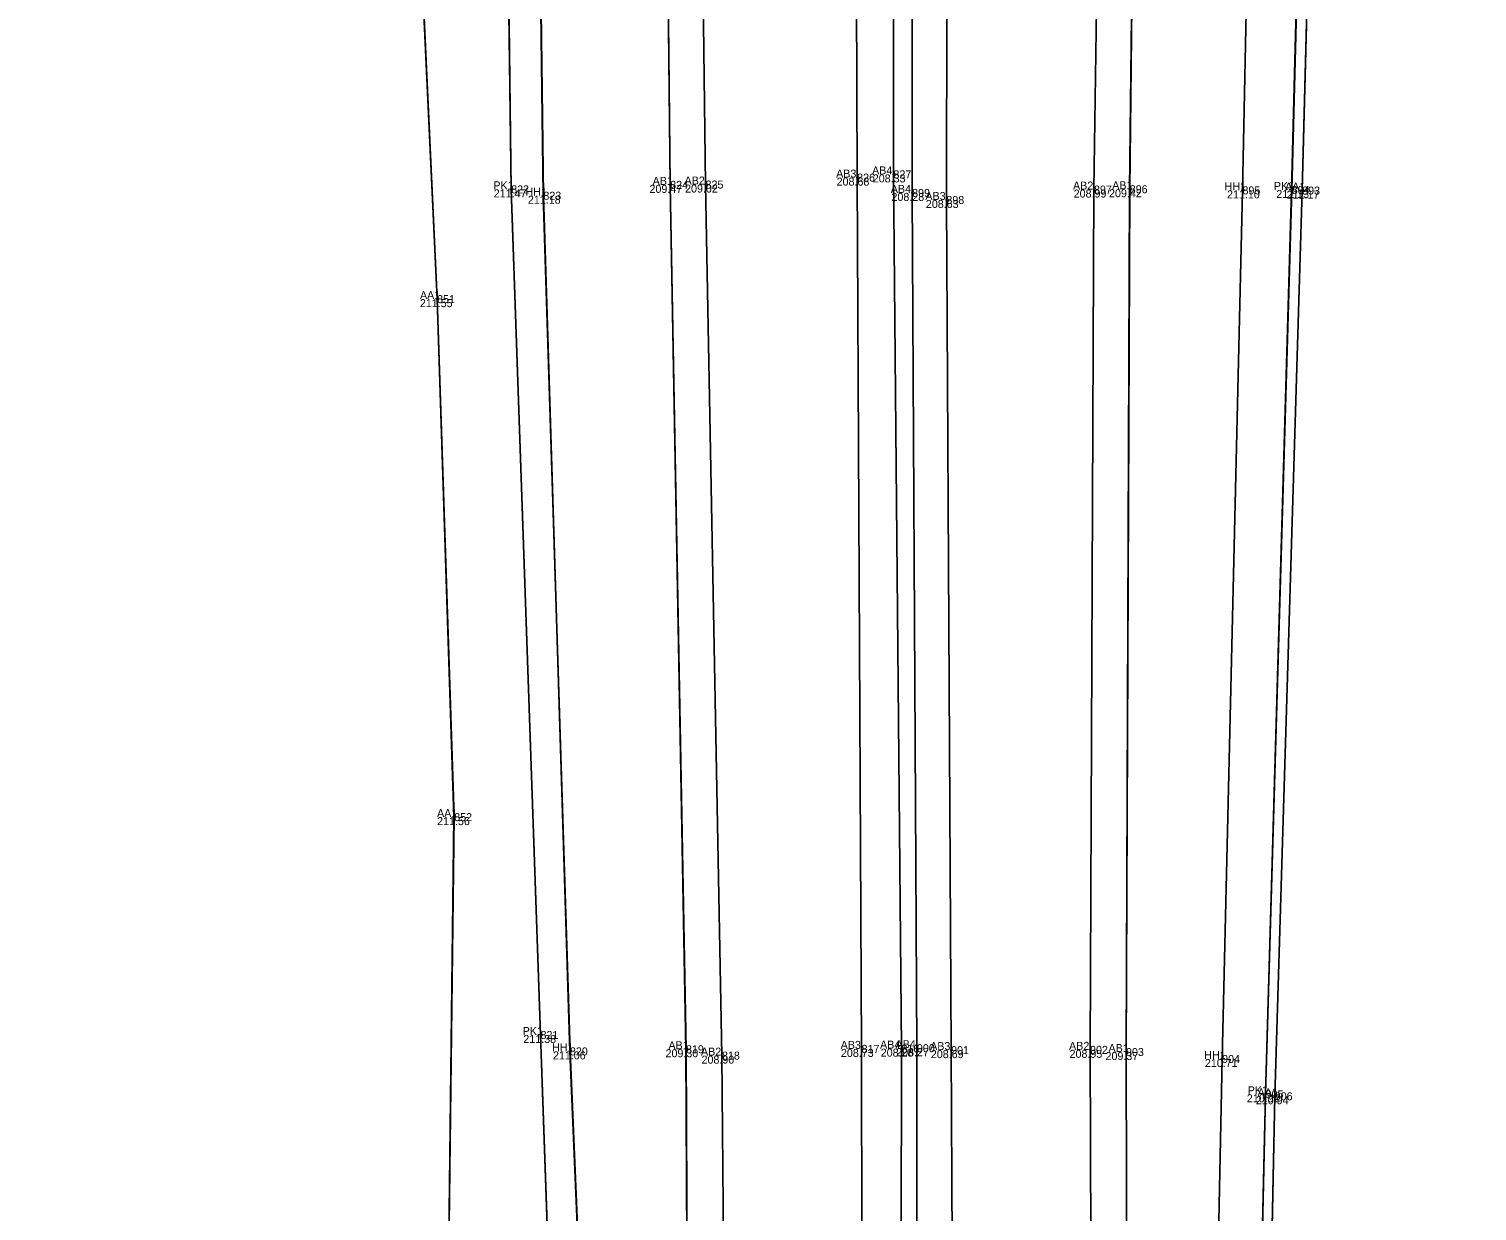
# Model space of a CAD drawing. Extents: x -263091 to -262565, y -1238731 to -1237092.
# Drawn here: x -262760.95 to -262724.75, y -1237381.76 to -1237352.21 of the extents above; entities that cross this region are included whole.
import ezdxf

# ---------------------------------------------------------------- set-up
doc = ezdxf.new("R2010")
doc.units = 0
for name, color, linetype in [('01_Hrana_betónu', 7, 'Continuous'), ('02_Oplotenie', 7, 'Continuous'), ('03_Asfalt', 7, 'Continuous'), ('05_Hrana_terénu', 7, 'Continuous'), ('Groma (21)', 7, 'Continuous'), ('Groma (22)', 7, 'Continuous'), ('Groma (23)', 7, 'Continuous'), ('Groma (24)', 7, 'Continuous'), ('U004_Asfalty', 7, 'Continuous'), ('U005_Betónové_panely', 7, 'Continuous'), ('U005_Zeleň_mimo', 7, 'Continuous'), ('U005_Zeleň_vnútro', 7, 'Continuous'), ('U005_Zeleň_zatrávňovač', 7, 'Continuous')]:
    doc.layers.add(name, color=color, linetype=linetype)

msp = doc.modelspace()

# ---------------------------------------------------------------- linework, layer by layer
at = {"layer": '01_Hrana_betónu'}
for points in [[(-262786.432, -1237675.911), (-262784.052, -1237670.991), (-262777.997, -1237658.39), (-262770.22, -1237641.884), (-262760.517, -1237621.621), (-262751.199, -1237602.266), (-262746.917, -1237592.345), (-262743.67, -1237583.59), (-262741.234, -1237574.416), (-262739.924, -1237566.213), (-262738.929, -1237556.596), (-262738.741, -1237547.665), (-262738.506, -1237524.618), (-262738.316, -1237501.393), (-262738.103, -1237478.98), (-262737.841, -1237459.175), (-262737.82, -1237425.07), (-262737.772, -1237401.714), (-262737.893, -1237377.738), (-262738.012, -1237356.488), (-262737.973, -1237332.295), (-262738.006, -1237318.022), (-262737.947, -1237310.645)], [(-262738.855, -1237311.192), (-262738.946, -1237318.051), (-262738.849, -1237332.413), (-262738.867, -1237356.312), (-262738.748, -1237377.69), (-262738.758, -1237401.69), (-262738.753, -1237425.185), (-262738.668, -1237459.096), (-262739.01, -1237478.875), (-262739.257, -1237501.361), (-262739.436, -1237524.506), (-262739.635, -1237547.624), (-262739.863, -1237556.5), (-262740.784, -1237566.075), (-262742.123, -1237574.161), (-262744.555, -1237583.315), (-262747.793, -1237592.067), (-262752.033, -1237601.877), (-262761.381, -1237621.164), (-262771.059, -1237641.465), (-262778.806, -1237657.918), (-262784.861, -1237670.667), (-262787.201, -1237675.529)], [(-262739.343, -1237311.485), (-262739.423, -1237318.909), (-262739.337, -1237332.42), (-262739.334, -1237355.849), (-262739.135, -1237377.701), (-262739.178, -1237401.786), (-262739.257, -1237424.031), (-262739.458, -1237458.924), (-262739.421, -1237479.296), (-262739.718, -1237500.116), (-262739.917, -1237524.824), (-262740.163, -1237546.913), (-262740.342, -1237556.649), (-262741.144, -1237564.78), (-262742.646, -1237573.838), (-262744.715, -1237582.455), (-262748.007, -1237591.229), (-262752.529, -1237601.669), (-262761.584, -1237620.386), (-262771.44, -1237641.076), (-262779.114, -1237657.574), (-262785.318, -1237670.364), (-262787.643, -1237675.31)], [(-262788.441, -1237674.914), (-262786.102, -1237669.974), (-262779.96, -1237657.146), (-262772.255, -1237640.671), (-262762.405, -1237620.082), (-262753.353, -1237601.237), (-262748.855, -1237590.92), (-262745.54, -1237582.117), (-262743.431, -1237573.688), (-262742.016, -1237564.7), (-262741.168, -1237556.501), (-262740.979, -1237546.892), (-262740.851, -1237524.752), (-262740.671, -1237500.08), (-262740.394, -1237479.483), (-262740.216, -1237458.955), (-262740.117, -1237423.647), (-262740.094, -1237401.75), (-262740.13, -1237377.708), (-262740.243, -1237355.929), (-262740.317, -1237332.345), (-262740.44, -1237318.894), (-262740.323, -1237312.076)], [(-262744.671, -1237314.693), (-262744.322, -1237332.28), (-262744.032, -1237356.103), (-262743.621, -1237377.876), (-262743.427, -1237401.834), (-262743.334, -1237423.507), (-262743.665, -1237455.163), (-262743.89, -1237458.66), (-262743.816, -1237479.543), (-262744.125, -1237500.374), (-262744.256, -1237524.891), (-262744.407, -1237545.149), (-262744.747, -1237556.085), (-262745.544, -1237564.593), (-262746.648, -1237572.023), (-262748.879, -1237581.03), (-262752.099, -1237589.665), (-262756.673, -1237599.828), (-262765.314, -1237617.226), (-262775.804, -1237639.013), (-262783.576, -1237655.372), (-262792.033, -1237673.09)], [(-262792.676, -1237672.47), (-262784.421, -1237654.971), (-262776.677, -1237638.569), (-262766.087, -1237616.912), (-262757.487, -1237599.378), (-262752.942, -1237589.379), (-262749.712, -1237580.796), (-262747.504, -1237571.715), (-262746.486, -1237564.414), (-262745.673, -1237555.98), (-262745.336, -1237545.322), (-262745.216, -1237524.737), (-262745.016, -1237500.506), (-262744.745, -1237479.418), (-262744.873, -1237458.479), (-262744.515, -1237455.206), (-262744.284, -1237423.517), (-262744.408, -1237401.828), (-262744.521, -1237377.717), (-262744.916, -1237356.111), (-262745.155, -1237332.402), (-262745.296, -1237327.881), (-262745.213, -1237324.651), (-262745.472, -1237315.175)], [(-262734.981, -1237524.159), (-262734.838, -1237501.704), (-262734.759, -1237479.135), (-262734.503, -1237458.564), (-262734.325, -1237455.231), (-262734.525, -1237425.166), (-262734.337, -1237401.529), (-262734.42, -1237377.731), (-262734.322, -1237356.228), (-262733.976, -1237332.423), (-262733.848, -1237318.408), (-262733.791, -1237315.943)], [(-262734.294, -1237524.216), (-262733.894, -1237501.859), (-262733.827, -1237479.2), (-262733.643, -1237458.579), (-262733.47, -1237455.059), (-262733.653, -1237425.263), (-262733.458, -1237401.537), (-262733.52, -1237377.786), (-262733.428, -1237356.22), (-262733.164, -1237332.492), (-262733.076, -1237318.46), (-262733.061, -1237316.012)]]:
    msp.add_lwpolyline(points, dxfattribs=at)
at = {"layer": '02_Oplotenie'}
for points in [[(-262728.456, -1237307.793), (-262728.519, -1237318.579), (-262728.768, -1237332.338), (-262729.377, -1237356.238), (-262730.032, -1237378.843), (-262730.564, -1237401.661), (-262730.923, -1237425.563), (-262730.973, -1237458.163), (-262731.252, -1237478.578), (-262731.235, -1237502.529), (-262731.31, -1237524.311), (-262731.953, -1237547.895), (-262732.188, -1237556.779), (-262732.808, -1237567.174), (-262734.162, -1237576.139), (-262736.979, -1237586.017), (-262740.293, -1237594.798), (-262745.086, -1237605.537), (-262753.698, -1237624.773), (-262762.903, -1237643.627), (-262772.016, -1237662.266), (-262776.478, -1237670.97)], [(-262793.971, -1237669.784), (-262786.051, -1237653.784), (-262778.339, -1237638.096), (-262767.839, -1237615.998), (-262759.49, -1237598.413), (-262754.828, -1237588.44), (-262751.768, -1237579.927), (-262749.971, -1237571.226), (-262749.021, -1237564.318), (-262748.215, -1237555.413), (-262747.787, -1237545.2), (-262747.818, -1237524.565), (-262747.681, -1237500.551), (-262747.391, -1237479.445), (-262747.231, -1237460.146), (-262746.875, -1237423.458), (-262747.304, -1237401.954), (-262748.156, -1237377.36), (-262748.89, -1237356.224), (-262749.247, -1237329.045)]]:
    msp.add_lwpolyline(points, dxfattribs=at)
at = {"layer": '03_Asfalt'}
for points in [[(-262724.746, -1237307.401), (-262727.828, -1237308.991), (-262728.093, -1237318.612), (-262728.491, -1237332.383), (-262729.117, -1237356.253), (-262729.803, -1237378.892), (-262730.272, -1237401.612), (-262730.633, -1237425.617), (-262730.625, -1237458.196), (-262731.018, -1237478.61), (-262730.917, -1237502.542), (-262731.001, -1237524.284), (-262731.468, -1237547.904), (-262731.892, -1237556.788), (-262732.535, -1237567.203), (-262733.679, -1237576.214), (-262736.504, -1237586.306), (-262740.104, -1237594.868), (-262744.783, -1237605.686), (-262753.189, -1237625.134), (-262761.527, -1237644.232), (-262769.984, -1237663.306), (-262774.379, -1237673.302), (-262777.928, -1237681.411)], [(-262754.337, -1237389.099), (-262750.532, -1237389.552), (-262750.315, -1237371.914), (-262750.742, -1237358.967), (-262751.363, -1237345.612), (-262751.817, -1237337.772), (-262753.202, -1237330.366), (-262753.43, -1237323.612), (-262753.446, -1237319.936)]]:
    msp.add_lwpolyline(points, dxfattribs=at)
at = {"layer": '05_Hrana_terénu'}
for points in [[(-262732.158, -1237524.14), (-262732.188, -1237502.434), (-262731.959, -1237478.777), (-262732.053, -1237459.14), (-262731.584, -1237456.865), (-262731.969, -1237454.761), (-262731.801, -1237425.623), (-262731.599, -1237401.469), (-262731.118, -1237377.96), (-262730.609, -1237356.249), (-262730.116, -1237332.328), (-262729.995, -1237318.493), (-262729.995, -1237315.948), (-262731.833, -1237314.756), (-262731.924, -1237311.037), (-262731.369, -1237306.686)], [(-262747.72, -1237316.528), (-262747.943, -1237319.204), (-262748.116, -1237323.022), (-262750.02, -1237324.88), (-262749.866, -1237328.115), (-262748.422, -1237329.259), (-262748.386, -1237332.654), (-262748.086, -1237356.382), (-262747.422, -1237377.77), (-262746.398, -1237401.993), (-262746.033, -1237423.594), (-262746.334, -1237453.039), (-262746.984, -1237457.232), (-262746.392, -1237460.215), (-262746.316, -1237479.567), (-262746.684, -1237500.449), (-262746.883, -1237524.672)]]:
    msp.add_lwpolyline(points, dxfattribs=at)
at = {"layer": 'Groma (21)'}
for centre in [(-262744.916, -1237356.111), (-262744.032, -1237356.103), (-262740.243, -1237355.929), (-262739.334, -1237355.849), (-262748.89, -1237356.224), (-262748.086, -1237356.382), (-262738.867, -1237356.312), (-262738.012, -1237356.488), (-262734.322, -1237356.228), (-262733.428, -1237356.22), (-262730.609, -1237356.249), (-262729.377, -1237356.238), (-262729.117, -1237356.253), (-262750.742, -1237358.967), (-262750.315, -1237371.914), (-262748.156, -1237377.36), (-262747.422, -1237377.77), (-262744.521, -1237377.717), (-262743.621, -1237377.876), (-262740.13, -1237377.708), (-262739.135, -1237377.701), (-262738.748, -1237377.69), (-262737.893, -1237377.738), (-262734.42, -1237377.731), (-262733.52, -1237377.786), (-262731.118, -1237377.96), (-262730.032, -1237378.843), (-262729.803, -1237378.892)]:
    msp.add_circle(centre, 0.01, dxfattribs=at)
at = {"layer": 'U004_Asfalty'}
for points in [[(-262732.04, -1237455.15), (-262733.47, -1237455.06), (-262733.65, -1237425.26), (-262733.46, -1237401.54), (-262733.52, -1237377.79), (-262733.43, -1237356.22), (-262733.16, -1237332.49), (-262733.08, -1237318.46), (-262733.06, -1237316.01), (-262732.65, -1237316.05), (-262730, -1237315.95), (-262730, -1237318.49), (-262730.12, -1237332.33), (-262730.61, -1237356.25), (-262731.12, -1237377.96), (-262731.6, -1237401.47), (-262731.8, -1237425.62), (-262731.97, -1237454.76), (-262732.04, -1237455.15)], [(-262745.77, -1237455.34), (-262746.33, -1237453.04), (-262746.03, -1237423.59), (-262746.4, -1237401.99), (-262747.42, -1237377.77), (-262748.09, -1237356.38), (-262748.39, -1237332.65), (-262748.42, -1237329.26), (-262746.92, -1237327.61), (-262745.3, -1237327.88), (-262745.16, -1237332.4), (-262744.92, -1237356.11), (-262744.52, -1237377.72), (-262744.41, -1237401.83), (-262744.28, -1237423.52), (-262744.52, -1237455.21), (-262745.77, -1237455.34)]]:
    msp.add_lwpolyline(points, dxfattribs=at)
at = {"layer": 'U005_Betónové_panely'}
msp.add_lwpolyline([(-262744.41, -1237401.83), (-262744.52, -1237377.72), (-262744.92, -1237356.11), (-262745.16, -1237332.4), (-262745.3, -1237327.88), (-262745.21, -1237324.65), (-262745.47, -1237315.17), (-262744.67, -1237314.69), (-262740.32, -1237312.08), (-262739.34, -1237311.49), (-262738.85, -1237311.19), (-262737.95, -1237310.65), (-262733.65, -1237308.06), (-262733.71, -1237310.85), (-262733.79, -1237315.94), (-262733.06, -1237316.01), (-262733.08, -1237318.46), (-262733.16, -1237332.49), (-262733.43, -1237356.22), (-262733.52, -1237377.79), (-262733.46, -1237401.54)], dxfattribs=at)
msp.add_lwpolyline([(-262744.41, -1237401.83), (-262744.52, -1237377.72), (-262744.92, -1237356.11), (-262745.16, -1237332.4), (-262745.3, -1237327.88), (-262745.21, -1237324.65), (-262745.47, -1237315.17), (-262744.67, -1237314.69), (-262740.32, -1237312.08), (-262739.34, -1237311.49), (-262738.85, -1237311.19), (-262737.95, -1237310.65), (-262733.65, -1237308.06), (-262733.71, -1237310.85), (-262733.79, -1237315.94), (-262733.06, -1237316.01), (-262733.08, -1237318.46), (-262733.16, -1237332.49), (-262733.43, -1237356.22), (-262733.52, -1237377.79), (-262733.46, -1237401.54)], dxfattribs=at)
at = {"layer": 'U005_Zeleň_mimo'}
for points in [[(-262731.31, -1237524.31), (-262731.24, -1237502.53), (-262731.25, -1237478.58), (-262730.97, -1237458.16), (-262730.92, -1237425.56), (-262730.56, -1237401.66), (-262730.03, -1237378.84), (-262729.38, -1237356.24), (-262728.77, -1237332.34), (-262728.52, -1237318.58), (-262728.46, -1237307.79), (-262731.37, -1237306.69), (-262728.52, -1237304.97), (-262727.83, -1237308.99), (-262728.09, -1237318.61), (-262728.49, -1237332.38), (-262729.12, -1237356.25), (-262729.8, -1237378.89), (-262730.27, -1237401.61), (-262730.63, -1237425.62), (-262730.63, -1237458.2), (-262731.02, -1237478.61), (-262730.92, -1237502.54), (-262731, -1237524.28)], [(-262750.53, -1237389.55), (-262750.32, -1237371.91), (-262750.74, -1237358.97), (-262751.36, -1237345.61), (-262751.82, -1237337.77), (-262753.2, -1237330.37), (-262753.43, -1237323.61), (-262753.45, -1237319.94), (-262731.37, -1237306.69), (-262747.72, -1237316.53), (-262747.94, -1237319.2), (-262748.12, -1237323.02), (-262750.02, -1237324.88), (-262749.87, -1237328.12), (-262749.25, -1237329.05), (-262748.89, -1237356.22), (-262748.16, -1237377.36), (-262747.3, -1237401.95)]]:
    msp.add_lwpolyline(points, dxfattribs=at)
at = {"layer": 'U005_Zeleň_vnútro'}
for points in [[(-262731.6, -1237401.47), (-262731.12, -1237377.96), (-262730.61, -1237356.25), (-262730.12, -1237332.33), (-262730, -1237318.49), (-262730, -1237315.95), (-262732.65, -1237316.05), (-262732.63, -1237315.56), (-262733.25, -1237315), (-262733.3, -1237309.06), (-262733.28, -1237307.83), (-262731.37, -1237306.69), (-262728.46, -1237307.79), (-262728.52, -1237318.58), (-262728.77, -1237332.34), (-262729.38, -1237356.24), (-262730.03, -1237378.84), (-262730.56, -1237401.66)], [(-262731.6, -1237401.47), (-262731.12, -1237377.96), (-262730.61, -1237356.25), (-262730.12, -1237332.33), (-262730, -1237318.49), (-262730, -1237315.95), (-262732.65, -1237316.05), (-262732.63, -1237315.56), (-262733.25, -1237315), (-262733.3, -1237309.06), (-262733.28, -1237307.83), (-262731.37, -1237306.69), (-262728.46, -1237307.79), (-262728.52, -1237318.58), (-262728.77, -1237332.34), (-262729.38, -1237356.24), (-262730.03, -1237378.84), (-262730.56, -1237401.66)], [(-262747.3, -1237401.95), (-262748.16, -1237377.36), (-262748.89, -1237356.22), (-262749.25, -1237329.05), (-262749.87, -1237328.12), (-262750.02, -1237324.88), (-262748.12, -1237323.02), (-262747, -1237325.47), (-262746.92, -1237327.61), (-262748.42, -1237329.26), (-262748.39, -1237332.65), (-262748.09, -1237356.38), (-262747.42, -1237377.77), (-262746.4, -1237401.99)], [(-262747.3, -1237401.95), (-262748.16, -1237377.36), (-262748.89, -1237356.22), (-262749.25, -1237329.05), (-262749.87, -1237328.12), (-262750.02, -1237324.88), (-262748.12, -1237323.02), (-262747, -1237325.47), (-262746.92, -1237327.61), (-262748.42, -1237329.26), (-262748.39, -1237332.65), (-262748.09, -1237356.38), (-262747.42, -1237377.77), (-262746.4, -1237401.99)]]:
    msp.add_lwpolyline(points, dxfattribs=at)
at = {"layer": 'U005_Zeleň_zatrávňovač'}
for points in [[(-262732.04, -1237455.15), (-262733.47, -1237455.06), (-262733.65, -1237425.26), (-262733.46, -1237401.54), (-262733.52, -1237377.79), (-262733.43, -1237356.22), (-262733.16, -1237332.49), (-262733.08, -1237318.46), (-262733.06, -1237316.01), (-262732.65, -1237316.05), (-262730, -1237315.95), (-262730, -1237318.49), (-262730.12, -1237332.33), (-262730.61, -1237356.25), (-262731.12, -1237377.96), (-262731.6, -1237401.47), (-262731.8, -1237425.62), (-262731.97, -1237454.76)], [(-262746.33, -1237453.04), (-262746.03, -1237423.59), (-262746.4, -1237401.99), (-262747.42, -1237377.77), (-262748.09, -1237356.38), (-262748.39, -1237332.65), (-262748.42, -1237329.26), (-262746.92, -1237327.61), (-262745.3, -1237327.88), (-262745.16, -1237332.4), (-262744.92, -1237356.11), (-262744.52, -1237377.72), (-262744.41, -1237401.83), (-262744.28, -1237423.52), (-262744.52, -1237455.21), (-262745.77, -1237455.34)]]:
    msp.add_lwpolyline(points, close=True, dxfattribs=at)

# ---------------------------------------------------------------- texts
at = {"layer": 'Groma (22)'}
for s, p in [('826', (-262740.243, -1237356.029)), ('827', (-262739.334, -1237355.949)), ('822', (-262748.89, -1237356.324)), ('824', (-262744.916, -1237356.211)), ('825', (-262744.032, -1237356.203)), ('897', (-262734.322, -1237356.328)), ('896', (-262733.428, -1237356.32)), ('895', (-262730.609, -1237356.349)), ('894', (-262729.377, -1237356.338)), ('893', (-262729.117, -1237356.353)), ('823', (-262748.086, -1237356.482)), ('899', (-262738.867, -1237356.412)), ('898', (-262738.012, -1237356.588)), ('851', (-262750.742, -1237359.067)), ('852', (-262750.315, -1237372.014)), ('821', (-262748.156, -1237377.46)), ('820', (-262747.422, -1237377.87)), ('819', (-262744.521, -1237377.817)), ('818', (-262743.621, -1237377.976)), ('817', (-262740.13, -1237377.808)), ('816', (-262739.135, -1237377.801)), ('900', (-262738.748, -1237377.79)), ('901', (-262737.893, -1237377.838)), ('902', (-262734.42, -1237377.831)), ('903', (-262733.52, -1237377.886)), ('904', (-262731.118, -1237378.06)), ('905', (-262730.032, -1237378.943)), ('906', (-262729.803, -1237378.992))]:
    msp.add_text(s, height=0.2, dxfattribs=at).set_placement(p)
at = {"layer": 'Groma (23)'}
for s, p in [('209.47', (-262745.433, -1237356.311)), ('209.02', (-262744.543, -1237356.303)), ('208.68', (-262740.755, -1237356.129)), ('208.33', (-262739.851, -1237356.049)), ('211.47', (-262749.326, -1237356.424)), ('211.18', (-262748.473, -1237356.582)), ('208.28', (-262739.384, -1237356.512)), ('208.63', (-262738.524, -1237356.688)), ('208.99', (-262734.829, -1237356.428)), ('209.42', (-262733.945, -1237356.42)), ('211.10', (-262730.996, -1237356.449)), ('211.13', (-262729.764, -1237356.438)), ('211.17', (-262729.505, -1237356.453)), ('211.55', (-262751.173, -1237359.167)), ('211.56', (-262750.741, -1237372.114)), ('211.38', (-262748.587, -1237377.56)), ('211.06', (-262747.847, -1237377.97)), ('209.30', (-262745.032, -1237377.917)), ('208.90', (-262744.132, -1237378.076)), ('208.73', (-262740.647, -1237377.908)), ('208.28', (-262739.652, -1237377.901)), ('208.27', (-262739.265, -1237377.89)), ('208.69', (-262738.4, -1237377.938)), ('208.95', (-262734.932, -1237377.931)), ('209.37', (-262734.033, -1237377.986)), ('210.71', (-262731.549, -1237378.16)), ('210.92', (-262730.5, -1237379.043)), ('210.94', (-262730.276, -1237379.092))]:
    msp.add_text(s, height=0.2, dxfattribs=at).set_placement(p)
at = {"layer": 'Groma (24)'}
for s, p in [('AB3', (-262740.767, -1237355.929)), ('AB4', (-262739.868, -1237355.849)), ('PK1', (-262749.337, -1237356.224)), ('HH1', (-262748.533, -1237356.382)), ('AB1', (-262745.354, -1237356.111)), ('AB2', (-262744.556, -1237356.103)), ('AB4', (-262739.401, -1237356.312)), ('AB2', (-262734.846, -1237356.228)), ('AB1', (-262733.866, -1237356.22)), ('HH1', (-262731.056, -1237356.249)), ('PK1', (-262729.824, -1237356.238)), ('AA1', (-262729.545, -1237356.253)), ('AB3', (-262738.536, -1237356.488)), ('AA1', (-262751.17, -1237358.967)), ('AA1', (-262750.743, -1237371.914)), ('PK1', (-262748.603, -1237377.36)), ('AB1', (-262744.959, -1237377.717)), ('AB3', (-262740.654, -1237377.708)), ('AB4', (-262739.669, -1237377.701)), ('AB4', (-262739.282, -1237377.69)), ('AB3', (-262738.417, -1237377.738)), ('AB2', (-262734.944, -1237377.731)), ('HH1', (-262747.869, -1237377.77)), ('AB2', (-262744.145, -1237377.876)), ('AB1', (-262733.958, -1237377.786)), ('HH1', (-262731.565, -1237377.96)), ('PK1', (-262730.479, -1237378.843)), ('AA1', (-262730.231, -1237378.892))]:
    msp.add_text(s, height=0.2, dxfattribs=at).set_placement(p)

doc.saveas('drawing.dxf')
